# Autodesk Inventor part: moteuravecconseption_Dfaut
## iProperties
Created: 2007-07
Part Number: moteuravecconseption_Dfaut
Document SubType Name: Modeling
Designer: EF
Density: 1 g/cm^3
Author: EF
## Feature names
1. Base1
2. Extrusion1
3. Perçage1 [Hole]
